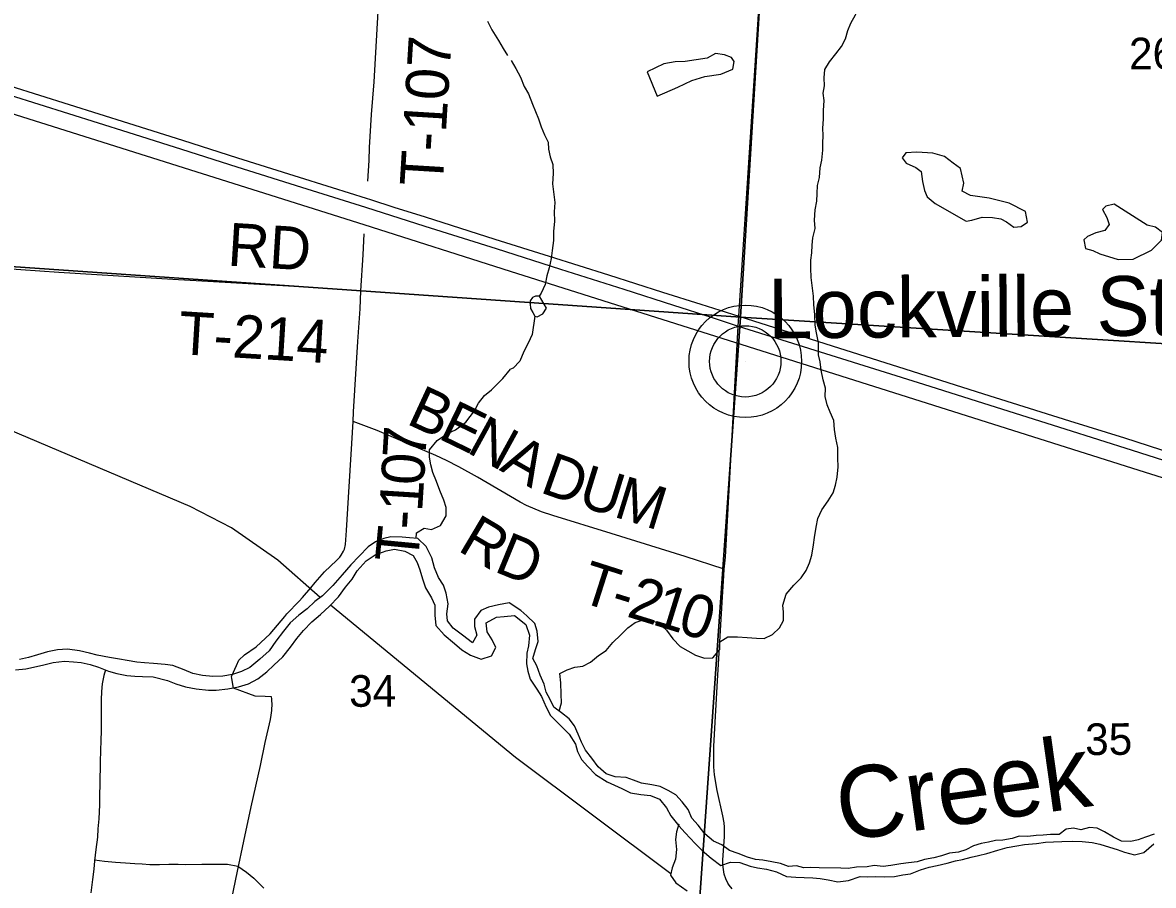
# Model space of a CAD drawing. Extents: x 114843 to 284848, y 317643 to 566895.
# Drawn here: x 272976 to 280872, y 336678 to 342702 of the extents above; entities that cross this region are included whole.
import ezdxf

# ---------------------------------------------------------------- set-up
doc = ezdxf.new("R2010")
doc.units = 0
for name, color, linetype in [('GM_X_County_Road', 7, 'Continuous'), ('GM_X_Minor_Lake', 7, 'Continuous'), ('GM_X_Minor_River', 7, 'Continuous'), ('GM_X_Minor_River_Text', 7, 'Continuous'), ('GM_X_Rail_Line', 7, 'Continuous'), ('GM_X_Section', 7, 'Continuous'), ('GM_X_Section_Text', 7, 'Continuous'), ('GM_X_Township_Road', 7, 'Continuous'), ('GM_X_Township_Road_Text', 7, 'Continuous'), ('GM_X_Unincorporated', 7, 'Continuous'), ('GM_X_Unincorporated_Location', 7, 'Continuous'), ('GM_X_Unincorporated_Text', 7, 'Continuous'), ('GM_X_US_Route', 7, 'Continuous')]:
    doc.layers.add(name, color=color, linetype=linetype)

msp = doc.modelspace()

# ---------------------------------------------------------------- linework, layer by layer
at = {"layer": 'GM_X_County_Road'}
for points in [[(277972, 340581.9), (277976.6, 340651.5), (278149.9, 343298.4)], [(277929.9, 336652.8), (277909.6, 336679.3), (277900.9, 336693.7), (277886.5, 336723.8), (277875.9, 336755.5), (277869.3, 336788.2), (277866.5, 336821.4), (277866.8, 336854.6), (277876.8, 337018.3), (277877.7, 337050.8), (277876.9, 337083.2), (277873.9, 337115.4), (277865.8, 337163.4), (277825.8, 337339.4), (277806.5, 337449.8), (277802.9, 337505.3), (277803.5, 337648.7), (277828, 338106.3), (277861.3, 338653.5), (277872.1, 338841.1), (277876.1, 338886.6), (277883.3, 338970.5), (277972, 340581.9)]]:
    msp.add_lwpolyline(points, dxfattribs=at)
at = {"layer": 'GM_X_Minor_Lake'}
for points in [[(277407.5, 342187.6), (277551.9, 342251.1), (277650.2, 342296.8), (277740.4, 342324.5), (277852.5, 342342.1), (277934.7, 342377.9), (277945, 342429.9), (277925.1, 342458.1), (277877.1, 342476.3), (277815.1, 342486.6), (277756.9, 342452.7), (277678.8, 342441), (277602.7, 342431.3), (277532.6, 342427.6), (277452.5, 342413.9), (277338.2, 342358.2)], [(277338.2, 342358.2), (277407.5, 342187.6)], [(279565.5, 341315), (279603.5, 341322.9), (279675.7, 341342.6), (279747.7, 341340.3), (279807.7, 341332.1), (279847.7, 341309.9), (279897.6, 341273.6), (279949.6, 341277.4), (279993.8, 341309.3), (279980.1, 341383.5), (279866.2, 341442.1), (279726.3, 341476.7), (279596.3, 341495.3), (279536.3, 341525.6), (279548.6, 341581.7), (279525, 341684), (279473.1, 341720.2), (279413.3, 341766.6), (279333.3, 341791), (279219.3, 341797.4), (279143.2, 341791.7), (279119, 341757.8), (279146.9, 341719.6), (279212.8, 341691.2), (279250.7, 341663), (279260.4, 341592.9), (279274.2, 341530.7), (279292, 341486.5), (279347.8, 341438.2)], [(279347.8, 341438.2), (279565.5, 341315)], [(280598.8, 341435.1), (280540.7, 341421.3), (280516.6, 341397.4), (280546.4, 341341.1), (280564.2, 341292.9), (280534, 341251), (280469.8, 341233.2), (280411.7, 341209.4), (280387.6, 341185.4), (280399.3, 341125.2), (280449.3, 341111), (280499.2, 341086.8), (280627.2, 341048.2), (280731.2, 341049.8), (280859.6, 341113.4), (280930, 341183.2), (280936.2, 341235.3), (280888.3, 341273.6), (280828.4, 341287.9)], [(280828.4, 341287.9), (280598.8, 341435.1)], [(276584.8, 340792), (276556.8, 340792.1), (276536.7, 340782.1), (276520.6, 340760.2), (276520.5, 340738.1), (276522.4, 340706), (276538.3, 340677.9), (276552.2, 340651.8), (276570.2, 340647.7), (276608.3, 340667.6), (276634.5, 340707.6)], [(276634.5, 340707.6), (276584.8, 340792)]]:
    msp.add_lwpolyline(points, dxfattribs=at)
at = {"layer": 'GM_X_Minor_River'}
for points in [[(278655.8, 342483.2), (278694, 342535.1), (278722.3, 342589.1), (278738.6, 342647.2), (278758.8, 342699.2), (278791.1, 342757.2), (278819.3, 342813.2), (278847.6, 342865.2), (278877.8, 342917.2), (278904.1, 342973.2), (278898.1, 342977.2)], [(276222.2, 342712.4), (276251.9, 342652.2), (276299.5, 342578), (276331.2, 342521.9), (276361, 342471.8)], [(276722.5, 337894.8), (276738.7, 337953.2), (276736.9, 338013.4), (276733.3, 338091.6), (276727.5, 338157.7), (276779.7, 338183.6), (276831.8, 338201.4), (276887.9, 338209.2), (276942, 338237), (276998.3, 338282.9), (277050.5, 338316.8), (277096.8, 338372.7), (277153, 338426.6), (277203.3, 338476.5), (277253.5, 338512.4), (277309.6, 338532.2), (277363.6, 338528), (277415.6, 338509.7), (277471.4, 338459.4), (277517.2, 338399.1), (277567, 338346.7), (277620.9, 338314.4), (277674.9, 338286.2), (277736.8, 338263.9), (277796.9, 338265.6), (277845.1, 338323.6), (277845.4, 338377.7), (277899.6, 338413.5), (277967.6, 338413.3), (278035.7, 338409), (278099.7, 338402.7), (278153.7, 338402.5), (278211.9, 338430.3), (278262.1, 338476.2), (278288.4, 338528.2), (278288.6, 338584.3), (278284.8, 338634.5), (278307.2, 338710.5), (278361.5, 338774.5), (278411.8, 338824.4), (278448, 338876.3), (278470.3, 338930.4), (278486.5, 338982.4), (278498.8, 339056.5), (278505.1, 339106.6), (278517.4, 339178.7), (278529.6, 339238.8), (278557.9, 339298.8), (278602.2, 339362.8), (278636.5, 339418.7), (278652.8, 339472.8), (278663, 339528.9), (278671.3, 339601), (278669.6, 339661.1), (278667.9, 339735.3), (278654.2, 339799.5), (278644.4, 339859.7), (278640.7, 339923.8), (278614.9, 339982), (278595.1, 340032.2), (278579.4, 340090.4), (278581.6, 340148.5), (278565.9, 340206.7), (278552.1, 340274.9), (278544.4, 340333.1), (278534.6, 340383.2), (278533, 340465.4), (278519.3, 340535.6), (278509.5, 340589.8), (278507.8, 340663.9), (278502.1, 340732.1), (278498.3, 340792.2), (278492.6, 340848.4), (278482.9, 340922.6), (278481.2, 340986.7), (278479.4, 341042.8), (278487.6, 341094.9), (278489.9, 341149), (278494.1, 341199.1), (278510.4, 341265.2), (278506.7, 341323.3), (278511, 341393.5), (278521.2, 341455.5), (278523.5, 341509.6), (278527.7, 341563.7), (278540, 341619.8), (278546.3, 341687.9), (278556.5, 341742), (278564.8, 341810.1), (278565, 341860.2), (278567.3, 341914.3), (278563.5, 341964.4), (278569.8, 342028.5), (278568, 342088.7), (278572.3, 342158.8), (278566.5, 342209), (278574.7, 342261), (278573, 342317.1), (278577.3, 342375.2), (278609.5, 342427.2), (278655.8, 342483.2)], [(276387.8, 342438.2), (276419.6, 342382), (276453.3, 342321.7), (276479.1, 342255.5), (276508.9, 342205.2), (276536.6, 342133), (276558.4, 342080.8), (276578.2, 342030.6), (276595.9, 341974.4), (276619.7, 341918.2), (276645.5, 341868), (276649.3, 341817.9), (276659.1, 341763.7), (276678.9, 341711.5), (276680.6, 341647.4), (276676.3, 341575.3), (276684, 341521.1), (276691.7, 341446.9), (276687.4, 341380.8), (276689.2, 341314.6), (276682.9, 341244.5), (276682.6, 341180.4), (276674.3, 341110.3), (276668, 341054.2), (276653.7, 340990.1), (276635.5, 340934.1), (276625.2, 340874), (276596.9, 340811.9), (276582.2, 340792)], [(275054.7, 338688.1), (274759.2, 338948.6), (274434.8, 339173.8), (274146, 339322.8), (271314.9, 340522.6), (271161.4, 340555.2), (269028.3, 340563.9), (268908.7, 340600.4), (268516.2, 340757.7), (268350.7, 340786.3), (267347.7, 340989.6), (267116.6, 341102.4), (266746.6, 341397.8)], [(276552.2, 340651.8), (276533.6, 340523.6), (276505.3, 340463.6), (276477.1, 340405.6), (276448.7, 340337.5), (276401.1, 340289.1), (276382.6, 340282.3)], [(275724.9, 339100.4), (275725.7, 339139.7), (275779.7, 339171.5), (275831.6, 339163.4), (275893.5, 339191.2), (275933.7, 339257.1), (275933.9, 339315.1), (275918.2, 339367.2), (275890.5, 339435.4), (275866.8, 339497.5), (275841.1, 339561.6), (275827.3, 339613.7), (275817.5, 339667.7), (275817.7, 339719.8), (275871.8, 339783.7), (275943.9, 339833.4), (275997.9, 339859.3), (276069.9, 339913.1), (276132, 339990.9), (276160.2, 340044.9), (276200.3, 340098.8), (276250.3, 340138.7), (276328.5, 340216.5), (276382.6, 340282.3)], [(276372.4, 338651.3), (276298.5, 338637.5), (276228.6, 338619.7), (276174.6, 338597.9), (276132.5, 338536), (276132.3, 338485.9), (276148, 338423.8), (276117.9, 338371.9), (276048.3, 338424.2), (275982.6, 338474.4), (275942.9, 338524.6), (275937.1, 338574.6), (275947.3, 338644.6), (275933.7, 338718.7), (275913.9, 338772.8), (275880.2, 338827), (275852.5, 338895.1), (275832.8, 338965.2), (275793.2, 339043.4), (275735.6, 339099.6), (275677.7, 339103.8), (275625.8, 339108), (275548, 339112.2), (275498.1, 339100.4), (275440.1, 339076.6), (275388.1, 339040.7), (275326, 338976.9), (275267.9, 338915), (275207.8, 338845.1), (275141.6, 338771.3), (275069.5, 338699.5), (275017.5, 338659.6), (274963.4, 338607.7), (274905.4, 338563.9), (274845.3, 338510.1), (274797.2, 338452.2), (274745.1, 338382.3), (274696.9, 338316.4), (274632.8, 338256.6), (274562.8, 338198.7), (274504.8, 338170.9), (274440.9, 338151.1), (274373, 338139.3), (274305.1, 338135.5), (274231.3, 338143.8), (274165.5, 338158), (274103.7, 338182.2), (274024, 338212.5), (273970.2, 338220.7), (273890.4, 338226.9), (273826.5, 338231.1), (273772.7, 338237.3), (273704.9, 338247.5), (273653, 338257.7), (273583.2, 338269.9), (273495.5, 338286.2), (273441.7, 338298.4), (273373.9, 338314.6), (273290.1, 338326.9), (273218.3, 338323.1), (273150.4, 338309.3), (273080.5, 338287.5), (273016.5, 338267.7), (272954.6, 338255.9)], [(272926.4, 338181.9), (272998.3, 338189.7), (273072.2, 338205.5), (273124.1, 338217.3), (273190, 338233.1), (273267.9, 338242.9), (273331.7, 338238.7), (273385.6, 338234.5), (273447.4, 338220.3), (273505.2, 338202.1), (273574.9, 338173.9), (273634.7, 338157.7), (273702.5, 338143.4), (273760.3, 338139.3), (273812.2, 338137.1), (273888, 338134.9), (273987.7, 338108.5), (274045.5, 338084.3), (274113.3, 338064.1), (274187.1, 338049.8), (274272.8, 338041.6), (274326.7, 338041.4), (274408.5, 338051.1), (274482.4, 338062.9), (274554.3, 338084.7), (274618.3, 338120.5), (274680.4, 338168.3), (274730.4, 338214.2), (274792.5, 338274.1), (274846.7, 338339.9), (274890.8, 338401.8), (274936.9, 338457.7), (274995, 338517.6), (275055.1, 338569.4), (275119.1, 338627.3), (275181.3, 338693.1), (275231.4, 338759), (275277.5, 338816.9), (275311.6, 338874.8), (275375.8, 338942.7), (275437.8, 338984.5), (275515.7, 339014.3), (275573.6, 339024.1), (275645.4, 339011.9), (275703.2, 338981.6), (275730.9, 338931.5), (275750.7, 338881.4), (275768.4, 338817.3), (275790.1, 338755.2), (275831.7, 338685), (275855.5, 338634.9), (275855.2, 338564.9), (275860.9, 338492.8), (275920.6, 338426.6), (275992.2, 338366.3), (276043.9, 338322.1), (276103.6, 338285.9), (276177.3, 338257.6), (276251.3, 338281.4), (276279.4, 338339.4), (276255.7, 338391.5), (276220, 338447.6), (276212.2, 338511.7), (276286.2, 338551.5), (276338.1, 338555.3), (276410, 338563.1)], [(276417.2, 337571.2), (275126, 338634.6)], [(280878, 337034.4), (280817.9, 337014.6), (280765.7, 336994.8), (280715.7, 336983), (280649.6, 336987.2), (280593.7, 337013.5), (280531.8, 337051.9), (280479.9, 337078.1), (280425.9, 337082.4), (280365.7, 337066.6), (280313.7, 337076.8), (280263.7, 337071), (280213.5, 337033.1), (280153.4, 337033.4), (280103.4, 337027.5), (280053.3, 337025.7), (279995.2, 337018), (279935.2, 337022.2), (279885.1, 337004.4), (279821, 336992.6), (279770.9, 336990.8), (279720.8, 336979), (279668.8, 336969.2), (279616.6, 336953.4), (279562.5, 336925.5), (279510.4, 336909.7), (279448.3, 336901.9), (279392.2, 336884.1), (279338.1, 336870.3), (279273.9, 336858.5), (279223.8, 336842.7), (279161.8, 336834.9), (279109.7, 336827.1), (279039.6, 336815.4), (278985.5, 336809.6), (278923.5, 336815.8), (278873.4, 336808), (278799.3, 336804.3), (278741.2, 336794.5), (278689.2, 336798.8), (278539.1, 336799.4), (278481.1, 336803.6), (278431, 336799.8), (278379, 336814), (278325, 336810.3), (278269, 336830.5), (278207, 336842.8), (278145, 336853.1), (278093, 336857.3), (278039, 336873.6), (277973.1, 336899.9), (277913.1, 336920.2), (277859.3, 336960.5), (277801.3, 336986.8), (277739.5, 337037.1), (277693.7, 337097.5), (277649.9, 337147.8), (277624.1, 337208), (277582.3, 337260.3), (277538.5, 337310.6), (277484.6, 337340.9), (277428.7, 337367.1), (277368.7, 337379.4), (277298.7, 337391.7), (277242.7, 337412), (277190.8, 337430.2), (277112.7, 337436.6), (277050.8, 337456.9), (276994.9, 337505.2), (276951.1, 337565.5), (276907.4, 337621.8), (276879.6, 337678), (276855.8, 337732.3), (276830, 337790.5), (276792.2, 337840.7), (276738.4, 337883.1), (276686.5, 337921.4), (276658.7, 337975.6), (276630.9, 338025.8), (276619.1, 338082), (276589.4, 338146.2), (276565.6, 338210.5), (276539.8, 338262.7), (276558.1, 338324.8), (276576.4, 338380.8), (276568.7, 338453), (276552.9, 338507.2), (276497.1, 338560.6), (276455.2, 338597.8), (276372.4, 338651.3)], [(276410, 338563.1), (276490.4, 338498.1), (276515, 338424.1), (276507.5, 338349.8), (276495.9, 338299.6), (276494.4, 338225.4), (276502.8, 338173.4), (276519.3, 338117.4), (276567.8, 338047.6), (276600.3, 337995.7), (276630.8, 337921.8), (276661.3, 337863.9), (276723.8, 337804.3), (276792.4, 337732.7), (276837, 337662.9), (276851.4, 337612.9), (276879.8, 337557), (276922.2, 337507.2), (276976.7, 337451.5), (277057.2, 337400.1), (277109.4, 337378.4), (277159.6, 337354.8), (277221.9, 337323.2), (277292.1, 337311.8), (277360.3, 337304.3), (277424.5, 337278.8), (277473, 337219), (277503.5, 337163.2), (277558, 337093.4), (277602.5, 337043.7), (277673.1, 336970.1), (277721.5, 336920.3), (277784, 336866.7), (277852.4, 336817.2), (277920.3, 336839.8), (277984.4, 336836.3), (278056.7, 336810.8), (278106.9, 336799.2), (278171, 336789.7), (278241.2, 336772.3), (278309.5, 336740.7), (278375.7, 336735.3), (278433.8, 336733.7), (278493.8, 336730.2), (278545.9, 336726.7), (278602.1, 336717.1), (278668.3, 336701.6), (278742.3, 336712.2), (278824.2, 336739), (278878.3, 336737.4), (278934.3, 336739.9), (278996.4, 336736.4), (279064.5, 336739), (279122.4, 336751.5), (279176.5, 336757.9), (279246.3, 336786.6), (279306.3, 336805.1), (279362.3, 336815.6), (279432.2, 336832.2), (279490.2, 336848.7), (279540.2, 336859.2), (279600.1, 336873.7), (279652.1, 336886.2), (279710.1, 336900.7), (279786, 336923.3), (279851.9, 336941.9), (279917.9, 336954.5), (279971.9, 336963), (280056, 336969.7), (280118, 336978.2), (280174, 336982.7), (280232.1, 336983.2), (280304.1, 336985.8), (280374.2, 336984.3), (280444.4, 336976.9), (280498.5, 336965.3), (280566.8, 336943.8), (280619, 336928.2), (280671.1, 336908.6), (280739.4, 336891.1), (280805.3, 336907.7), (280875, 336968.4)], [(273555.4, 338181.8), (273542.9, 338144), (273530.7, 338085.9), (273526.5, 338031.9), (273524.3, 337973.9), (273523.8, 337855.8), (273525.4, 337761.7), (273521.2, 337683.7), (273518.9, 337623.7), (273516.6, 337535.6), (273516, 337389.5), (273513.7, 337303.4), (273513.5, 337239.4), (273507.1, 337141.3), (273500.9, 337073.3), (273498.6, 337013.3), (273486.3, 336927.3), (273478.1, 336849.2), (273473.9, 336791.2), (273463.6, 336719.2), (273453.3, 336625.1)], [(277502.5, 336757.2), (276417.2, 337571.2)], [(277548.6, 337105.5), (277558, 337105.5), (277542.3, 337051.2), (277534.7, 336999), (277543.2, 336928.9), (277535.7, 336860.7), (277512.1, 336800.3), (277500.5, 336748.1), (277537, 336694.3), (277617.5, 336638.8)], [(273478.8, 336855.9), (273547.9, 336847), (273623.7, 336840.7), (273693.5, 336834.5), (273759.4, 336830.3), (273811.2, 336828.1), (273863.1, 336824), (273930.9, 336823.7), (273996.8, 336825.5), (274062.7, 336825.3), (274114.5, 336823.2), (274226.3, 336826.8), (274346, 336826.4), (274405.9, 336826.2), (274477.7, 336812), (274539.4, 336769.8), (274591.1, 336727.6), (274660.7, 336659.3)]]:
    msp.add_lwpolyline(points, dxfattribs=at)
at = {"layer": 'GM_X_Rail_Line'}
msp.add_lwpolyline([(272708.4, 342128.9), (275357.5, 341291.3), (276381.4, 340967.5), (280815.6, 339562.2), (281482.6, 339352.5)], dxfattribs=at)
at = {"layer": 'GM_X_Section'}
for points in [[(272972.7, 346295), (278313.2, 345927.1), (277988.7, 340646.3), (272656.8, 341014.8)], [(278313.2, 345927.1), (283846.1, 345605.9), (283493.7, 340300.9), (277988.7, 340646.3)], [(272656.8, 341014.8), (277988.7, 340646.3), (277608.8, 335233.2), (272595.5, 335573.5), (272313.4, 335594.4)], [(283493.7, 340300.9), (283177.6, 334922.1), (277905, 335210.8), (277608.8, 335233.2), (277988.7, 340646.3)]]:
    msp.add_lwpolyline(points, close=True, dxfattribs=at)
at = {"layer": 'GM_X_Township_Road'}
for points in [[(275385.6, 341594.9), (275395.3, 341739.5), (275398.6, 341830.8), (275412.4, 342059.7), (275429.7, 342288.5), (275459.7, 342779.3), (275459.2, 342812.6), (275457.2, 342829.2), (275454, 342845.7), (275449.4, 342861.8), (275443.3, 342877.3), (275428.5, 342907.2), (275335.9, 343060.5), (275295.2, 343133.1), (275274.3, 343177.8), (275247.4, 343247.4), (275227, 343333.5), (275196.2, 343486.4)], [(274024.4, 340908.7), (273229.1, 340957.1), (271235.2, 341097.8), (269763.3, 341201.1), (269338.1, 341231.6), (268586, 341287.9), (268209.7, 341312.1), (267561.4, 341363.2)], [(274930.2, 338688.3), (274988.5, 338754.1), (275019, 338792.8), (275050.8, 338830.5), (275085.1, 338865.9), (275168.6, 338945.1), (275190.8, 338969.3), (275200.7, 338982.5), (275216.8, 339011), (275222.6, 339026.3), (275229.8, 339058.3), (275233.5, 339091), (275238.1, 339156.6), (275251, 339386.4), (275275.1, 339763.7), (275283.9, 339917.1), (275285.4, 339984.8), (275316.5, 340475.4), (275333.2, 340704), (275334.2, 340765.8), (275337, 340829), (275355, 341079.8), (275361.6, 341226.6)], [(275337, 340829), (275240.9, 340835.3), (274832.6, 340861.5), (274308.8, 340891.5), (274024.4, 340908.7)], [(277876.1, 338886.6), (277603.1, 338973.4), (277085, 339133.7), (276677.4, 339259.7), (276599.6, 339286.1), (276493.8, 339330.8), (276450.4, 339354.1), (276152.5, 339528.3), (276022.9, 339599.5), (275935.3, 339644.7), (275860.9, 339679.5), (275679.7, 339757), (275452.7, 339852.9), (275283.9, 339917.1)], [(274436.6, 338121.1), (274433.6, 338136.5), (274436, 338141.7), (274468.9, 338213.7), (274486.8, 338249.8), (274524.8, 338288), (274606.7, 338342.2), (274704.5, 338434.5), (274805.8, 338555.6), (274820.3, 338572.9), (274906.1, 338661.2), (274930.2, 338688.3)], [(274716.8, 337963.6), (274715.9, 337979.7), (274713.2, 337994.5), (274668.9, 337996.7), (274599.9, 337999.8), (274449.4, 338054.6), (274436.6, 338121.1)], [(274279.9, 335850.2), (274297.3, 335926.6), (274406.1, 336440.2), (274476.5, 336777.6), (274519.5, 336986.5), (274572.5, 337226.7), (274636, 337514.7), (274668.7, 337675.3), (274706.6, 337834.8), (274712.6, 337866.8), (274716.4, 337898.9), (274717.6, 337947.5), (274716.8, 337963.6)]]:
    msp.add_lwpolyline(points, dxfattribs=at)
at = {"layer": 'GM_X_Unincorporated'}
for radius in [392.9, 249.1]:
    msp.add_circle((278022.4, 340336.7), radius, dxfattribs=at)
at = {"layer": 'GM_X_Unincorporated_Location'}
msp.add_line((278022.4, 340336.7), (278022.4, 340336.7), dxfattribs=at)
at = {"layer": 'GM_X_US_Route'}
for points in [[(268854.1, 343538.2), (268965, 343502.9), (269191.9, 343431.2), (270130.5, 343134.4), (270697.6, 342954.4), (271181.7, 342802), (271638, 342656.7), (272094.8, 342512.9), (272583.7, 342357.7), (272887, 342261.2), (273300.5, 342130.7), (273715.4, 341999.3), (274091.2, 341881.3), (274477.4, 341758.2), (274870.7, 341635.2), (275137.7, 341550.2), (275374.3, 341475.7), (275404.1, 341466.1)], [(268860.7, 343470.3), (269186.8, 343368.1), (270125.4, 343071.3), (270692.4, 342891.2), (271154.9, 342744.2), (271632.9, 342593.6), (272089.7, 342449.8), (272578.6, 342294.5), (272881.9, 342198.1), (273295.4, 342067.6), (273710.3, 341936.2), (274086.1, 341818.2), (274472.2, 341695.1), (274922.5, 341553.1), (275369.2, 341412.6)], [(275404.1, 341466.1), (275568.1, 341413.3), (275786.2, 341345.4), (276273.6, 341190.6), (276653.2, 341071.6), (277066.2, 340941.2), (277445.3, 340820.3), (277712.8, 340735.3), (277976.6, 340651.5), (278629.8, 340446), (279136.5, 340283.8), (279685, 340110.6), (280286.6, 339921.2), (280669.7, 339801.5), (281095.4, 339665.6)], [(275369.2, 341412.6), (275784.8, 341279.8), (276281.6, 341123.7), (276730.9, 340981.3), (277174.1, 340840.2), (277521.2, 340729), (277784.4, 340646.3), (277972, 340581.9), (279267.6, 340177), (279730.8, 340031), (280254.9, 339864.5), (280724.2, 339716.8), (281439.8, 339489.2)]]:
    msp.add_lwpolyline(points, dxfattribs=at)

# ---------------------------------------------------------------- texts
at = {"layer": 'GM_X_Minor_River_Text'}
msp.add_text('Creek', height=500.03, rotation=7.99488, dxfattribs=at).set_placement((278692.9, 336985.1))
at = {"layer": 'GM_X_Section_Text'}
for s, rotation, p in [('26', 0.41499, (280703.1, 342375)), ('34', 0.41481, (275256.7, 337924.1)), ('35', 0.41491, (280396.7, 337587.3))]:
    msp.add_text(s, height=221.02, rotation=rotation, dxfattribs=at).set_placement(p)
at = {"layer": 'GM_X_Township_Road_Text'}
for s, height, rotation, p in [('T-107', 300.03, 86.49618, (275908.6, 341552.5)), ('RD', 300.03, 356.46886, (274402.4, 341005.6)), ('T-214', 300.03, 356.49159, (274057.9, 340388)), ('B', 300, 335.2428, (275647.3, 339904.6)), ('E', 300, 334.16413, (275869.7, 339802)), ('N', 300, 331.21942, (276068.1, 339706.1)), ('7', 300, 86.57967, (275788, 339651)), ('A', 300, 330.32387, (276298.4, 339579.6)), ('0', 300, 86.56154, (275776.9, 339466.4)), ('D', 300, 340.45854, (276580.4, 339424.8)), ('U', 300, 342.83037, (276842.1, 339332.2)), ('1', 300, 86.46059, (275765.4, 339281.3)), ('M', 300, 342.80094, (277094.3, 339254.3)), ('-', 300, 86.2028, (275757.2, 339156.9)), ('R', 300, 329.3085, (276005.9, 339020)), ('T', 300, 84.50294, (275734.9, 338923.9)), ('D', 300, 337.67435, (276259.9, 338873.3)), ('T', 300, 342.255, (276851.6, 338663.2)), ('2', 300, 342.81186, (277186, 338557.3)), ('-', 300, 342.73534, (277067.9, 338594)), ('1', 300, 342.83844, (277362.7, 338502.6)), ('0', 300, 342.84432, (277539.3, 338448))]:
    msp.add_text(s, height=height, rotation=rotation, dxfattribs=at).set_placement(p)
at = {"layer": 'GM_X_Unincorporated_Text'}
msp.add_text('Lockville Station', height=417.037, rotation=0.41491, dxfattribs=at).set_placement((278182, 340497))

doc.saveas('drawing.dxf')
